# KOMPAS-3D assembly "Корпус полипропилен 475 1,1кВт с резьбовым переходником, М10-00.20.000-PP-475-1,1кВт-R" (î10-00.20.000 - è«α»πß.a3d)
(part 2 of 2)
Referenced files in C:\Users\User\Desktop\Магна 10 для Караби\: М10-00.20.001 - Плита опорная.m3d, Колено 90гр 32 FV PPR ф. FV PLAST.m3d, М10-00.30.000 - Обечайка.a3d, Труба 32 PN10 S=2,9 FV PPR ф. FV PLAST.m3d, М10-00.25.001 - Колонна.m3d, М10-00.20.002 - Фланец.m3d, М10-00.20.002 - Фланец.cdw, М10-00.30.000 - Обечайка.cdw
Referenced files in D:\Magna\Магна Ins\Магна ins 10\М10-00.00.000\3Д\: М10-00.30.000 - Обечайка.cdw, М10-00.25.001 - Колонна.cdw, М10-00.20.002 - Фланец.cdw, М10-00.20.000 - Корпус.cdw, М10-00.30.000 - Обечайка.a3d, М10-00.20.001 - Плита опорная.m3d, Колено 90гр 32 FV PPR ф. FV PLAST.m3d, Труба 32 PN10 S=2,9 FV PPR ф. FV PLAST.m3d, М10-00.25.001 - Колонна.m3d
Referenced files in D:\Magna\Магна Ins\Магна ins 5\М5-00.00.000 - Насос Магна ins 5-C-N\3Д модель\: М5-00.10.002 - Фланец.m3d
Referenced files in D:\Magna\Магна Ins\Магна ins 5\М5-00.00.000 - Насос Магна ins 5-C-N\Чертежи\: М5-00.10.002 - Фланец.cdw
Referenced files in C:\Users\Магна ins 5\М5-00.00.000 - Насос Магна ins 5-C-N\3Д модель\..\Чертежи\: М5-00.10.002 - Фланец.cdw
Referenced files in D:\1 ПКИ 3D\Полипропиленовые фитинги, трубы\: Переходник с пластмассовой резьбой наружной 32х1 FV PPR ф.FV Plast.m3d
Referenced files in D:\1 ПКИ 3D\Полипропиленовые фитинги, трубы\Разборные муфты\: Муфта разъёмная 32.m3d
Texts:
  Body Specification ( left align )
  Body Specificaton ( centered )
  М10-00.25.001 - PP
  М10-00.25.001 - PP-375
  М10-00.25.001 - PP-425
  М10-00.25.001 - PP-475
  Переходник с пластмассовой резьбой
  наружной 32х1" FV PPR
  ф. "FV PLAST"
  габ. 71, 80
  @100~)3xA3
  PP-375
  PP-375-0,55кВт
  PP-375-0,55кВт-R
  PP-375-0,55кВт-M
  PP-375-0,75кВт
  PP-375-0,75кВт-R
  PP-375-0,75кВт-M
  PP-375-1,1кВт
  PP-375-1,1кВт-R
  PP-375-1,1кВт-M
  PP-425
  PP-425-0,55кВт
  PP-425-0,55кВт-M
  PP-425-0,55кВт-R
  PP-425-0,75кВт
  PP-425-0,75кВт-M
  PP-425-0,75кВт-R
  PP-425-1,1кВт
  PP-425-1,1кВт-M
  PP-425-1,1кВт-R
  PP-475
  PP-475-0,55кВт
  PP-475-0,55кВт-M
  PP-475-0,55кВт-R
  PP-475-0,75кВт
  PP-475-0,75кВт-M
  PP-475-0,75кВт-R
  PP-475-1,1кВт
  PP-475-1,1кВт-M
  PP-475-1,1кВт-R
